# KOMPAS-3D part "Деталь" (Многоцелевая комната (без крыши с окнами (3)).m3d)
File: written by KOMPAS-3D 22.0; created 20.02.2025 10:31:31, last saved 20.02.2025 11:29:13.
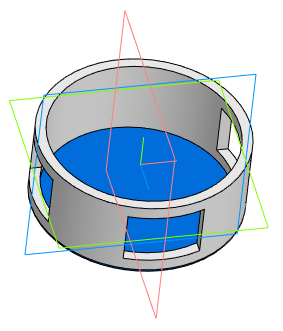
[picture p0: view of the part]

Document properties: Автор: Пользователь Windows; Полное имя файла: C:\Users\Student\Documents\Картошечка\База Сабнатика\Многоцелевая комната\Многоцелевая комната (без крыши с окнами (3)).m3d

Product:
- Part/product: Деталь
    Масса: 0.099908

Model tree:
1. Эскиз:3
2. Элемент вращения:1
     Угол 1 = 360
3. Скругление:1  (with: Элемент вращения:1)
     Радиус = 1
4. Эскиз:4  (with: Элемент вращения:1)
5. Элемент выдавливания:1
     Расстояние 2 = 6.1
6. Эскиз:5  (with: Элемент выдавливания:1)
7. Элемент выдавливания:2
     Расстояние 2 = 19
8. Эскиз:6
9. Элемент выдавливания:3
     Расстояние 1 = 25; Расстояние 2 = 25
10. Эскиз:7
11. Элемент выдавливания:4
     Расстояние 1 = 25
